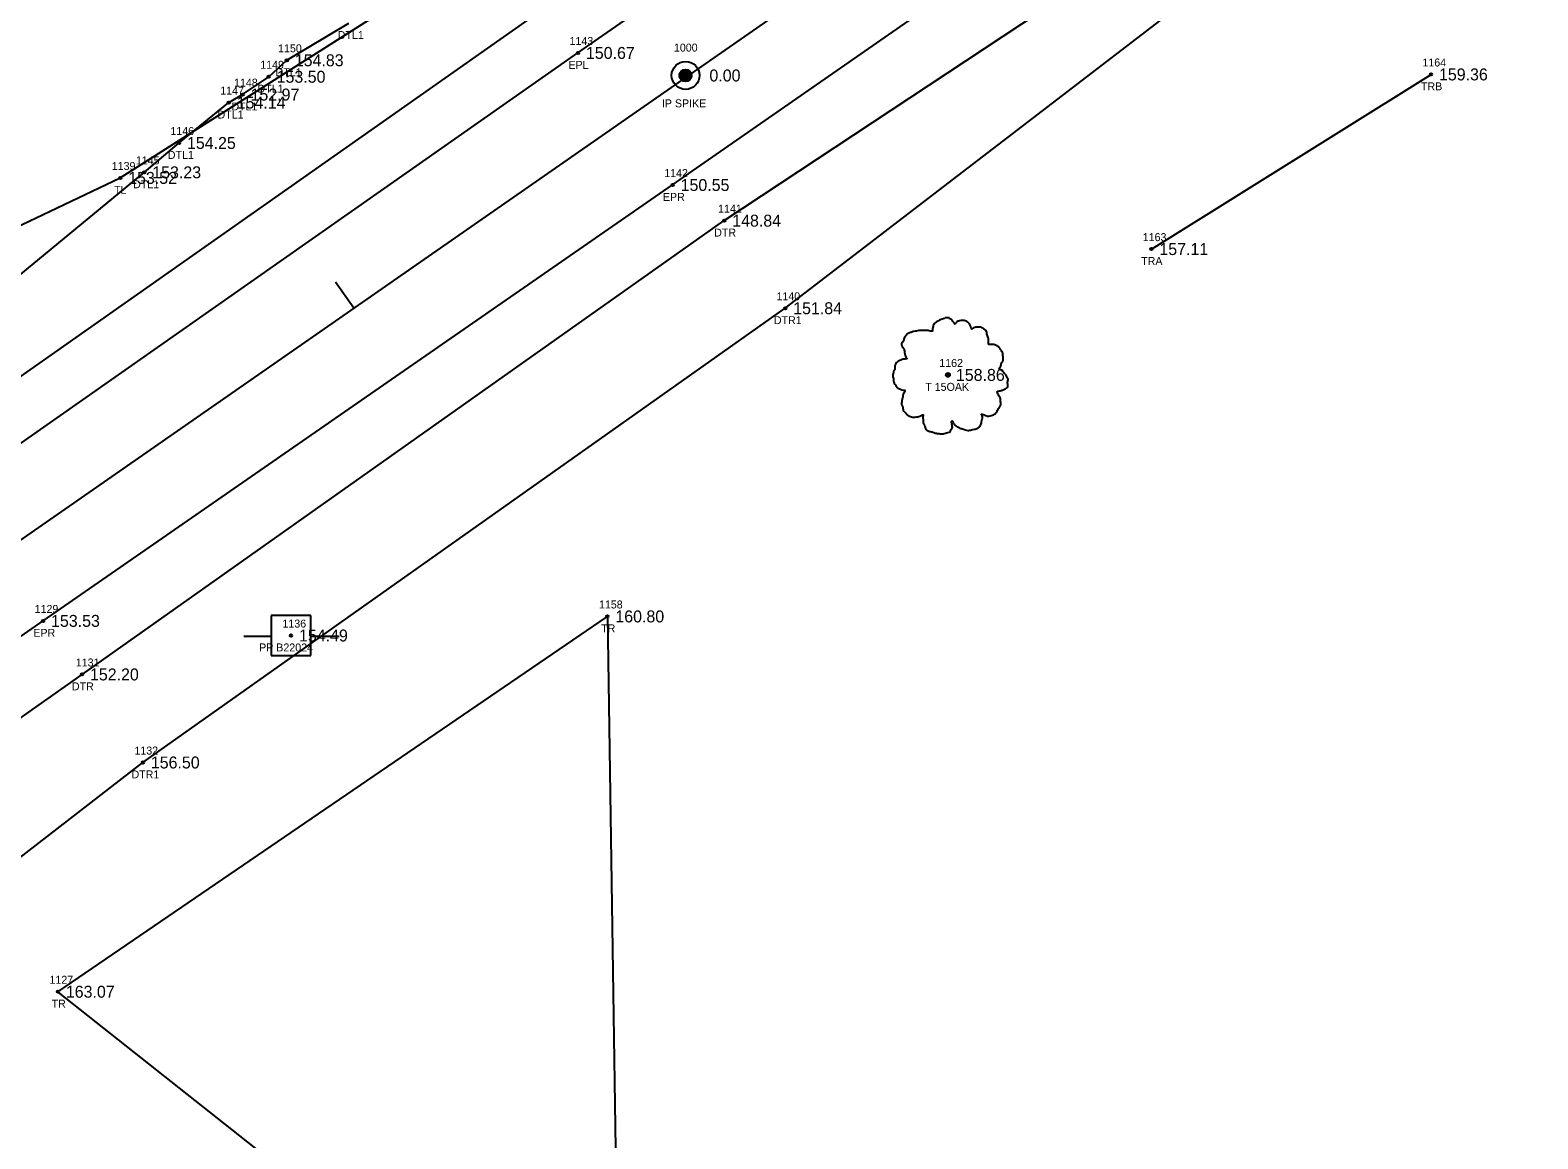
# Model space of a CAD drawing. Extents: x 2449052 to 2452984, y 1012343 to 1015262.
# Drawn here: x 2450486.8 to 2450676.2, y 1013470.3 to 1013609.6 of the extents above; entities that cross this region are included whole.
import ezdxf

# ---------------------------------------------------------------- set-up
doc = ezdxf.new("R2010")
doc.units = 0
for name, color, linetype in [('RD_EX_DV_Prop_txCode', 7, 'Continuous'), ('RD_EX_DV_PropPin', 7, 'Continuous'), ('RD_EX_H2O', 7, 'Continuous'), ('RD_EX_H2O_txCode', 7, 'Continuous'), ('RD_EX_Road', 7, 'Continuous'), ('RD_EX_Road_txCode', 7, 'Continuous'), ('RD_EX_TX_DV_Prop_ELEV', 7, 'Continuous'), ('RD_EX_TX_H2O_ELEV', 7, 'Continuous'), ('RD_EX_TX_Road_ELEV', 7, 'Continuous'), ('RD_EX_TX_VEG_ELEV', 7, 'Continuous'), ('RD_EX_UT', 7, 'Continuous'), ('RD_EX_UT_txCode', 7, 'Continuous'), ('RD_EX_VEG', 7, 'Continuous'), ('RD_EX_VEG_txCode', 7, 'Continuous'), ('RD_HC_Cl', 7, 'Continuous'), ('RD_HC_Data_Tic', 7, 'Continuous'), ('RD_HC_Survey_ELEV', 7, 'Continuous'), ('RD_SMD_Locator', 7, 'Continuous')]:
    doc.layers.add(name, color=color, linetype=linetype)

msp = doc.modelspace()

# ---------------------------------------------------------------- linework, layer by layer
at = {"layer": 'RD_EX_DV_PropPin'}
for p, q in [((2450568.38, 1013603.7), (2450568.38, 1013604.09)), ((2450568.42, 1013603.6), (2450568.42, 1013604.19)), ((2450568.45, 1013603.53), (2450568.45, 1013604.27)), ((2450568.49, 1013603.47), (2450568.49, 1013604.32)), ((2450568.52, 1013603.42), (2450568.52, 1013604.37)), ((2450568.56, 1013603.38), (2450568.56, 1013604.41)), ((2450568.59, 1013603.35), (2450568.59, 1013604.45)), ((2450568.63, 1013603.31), (2450568.63, 1013604.48)), ((2450568.66, 1013603.29), (2450568.66, 1013604.51)), ((2450568.7, 1013603.26), (2450568.7, 1013604.53)), ((2450568.73, 1013603.24), (2450568.73, 1013604.55)), ((2450568.77, 1013603.22), (2450568.77, 1013604.57)), ((2450568.8, 1013603.2), (2450568.8, 1013604.59)), ((2450568.84, 1013603.19), (2450568.84, 1013604.6)), ((2450568.87, 1013603.18), (2450568.87, 1013604.62)), ((2450568.91, 1013603.17), (2450568.91, 1013604.63)), ((2450568.94, 1013603.16), (2450568.94, 1013604.64)), ((2450568.98, 1013603.15), (2450568.98, 1013604.64)), ((2450569.01, 1013603.14), (2450569.01, 1013604.65)), ((2450569.05, 1013603.14), (2450569.05, 1013604.65)), ((2450569.08, 1013603.14), (2450569.08, 1013604.66)), ((2450569.12, 1013603.14), (2450569.12, 1013604.66)), ((2450569.15, 1013603.14), (2450569.15, 1013604.66)), ((2450569.19, 1013603.14), (2450569.19, 1013604.65)), ((2450569.22, 1013603.14), (2450569.22, 1013604.65)), ((2450569.26, 1013603.15), (2450569.26, 1013604.64)), ((2450569.29, 1013603.16), (2450569.29, 1013604.64)), ((2450569.33, 1013603.17), (2450569.33, 1013604.63)), ((2450569.36, 1013603.18), (2450569.36, 1013604.62)), ((2450569.4, 1013603.19), (2450569.4, 1013604.6)), ((2450569.44, 1013603.2), (2450569.44, 1013604.59)), ((2450569.47, 1013603.22), (2450569.47, 1013604.57)), ((2450569.51, 1013603.24), (2450569.51, 1013604.55)), ((2450569.54, 1013603.26), (2450569.54, 1013604.53)), ((2450569.58, 1013603.29), (2450569.58, 1013604.51)), ((2450569.61, 1013603.31), (2450569.61, 1013604.48)), ((2450569.65, 1013603.35), (2450569.65, 1013604.45)), ((2450569.68, 1013603.38), (2450569.68, 1013604.41)), ((2450569.72, 1013603.42), (2450569.72, 1013604.37)), ((2450569.75, 1013603.47), (2450569.75, 1013604.32)), ((2450569.79, 1013603.53), (2450569.79, 1013604.27)), ((2450569.82, 1013603.6), (2450569.82, 1013604.19)), ((2450569.86, 1013603.7), (2450569.86, 1013604.09))]:
    msp.add_line(p, q, dxfattribs=at)
for radius in [1.75, 0.761]:
    msp.add_circle((2450569.12, 1013603.9), radius, dxfattribs=at)
at = {"layer": 'RD_EX_H2O'}
for points in [[(2450167.46, 1013291.72), (2450167.1, 1013295.75), (2450175.19, 1013302.21), (2450253.51, 1013357.72), (2450334.87, 1013415.7), (2450415.19, 1013473.64), (2450493.27, 1013528.65), (2450573.99, 1013585.66), (2450651, 1013636.62), (2450748.48, 1013707.64), (2450786.48, 1013731.51)], [(2450167.46, 1013291.72), (2450171.71, 1013290.19), (2450180.8, 1013296.66), (2450259.89, 1013349.14), (2450344.33, 1013402.02), (2450412.23, 1013445.13), (2450424.15, 1013461.12), (2450474.5, 1013497.19), (2450500.92, 1013517.59), (2450581.65, 1013574.66), (2450655.67, 1013631.45), (2450753.63, 1013700.7), (2450792.21, 1013722.47), (2450790.93, 1013725.57), (2450786.48, 1013731.51)], [(2450082.81, 1013302.86), (2450086.85, 1013297.03), (2450148.02, 1013337.87), (2450230.55, 1013392.65), (2450311.52, 1013448.88), (2450394.54, 1013504.43), (2450473.16, 1013557.42), (2450552.01, 1013612.78), (2450577.68, 1013632.73), (2450594.53, 1013644.88)], [(2450469.06, 1013565.35), (2450501.1, 1013591.73), (2450505.46, 1013595.42), (2450511.71, 1013600.49), (2450513.45, 1013601.5), (2450516.73, 1013603.74), (2450519.01, 1013605.81), (2450526.82, 1013610.48)]]:
    msp.add_lwpolyline(points, dxfattribs=at)
at = {"layer": 'RD_EX_Road'}
for points in [[(2449674.89, 1012994.69), (2449752.35, 1013048.28), (2449834.92, 1013105.96), (2449914.72, 1013161.11), (2449995.66, 1013217.59), (2450075.29, 1013272.9), (2450081.34, 1013277.24), (2450093.41, 1013285.64), (2450155.49, 1013328.69), (2450236.05, 1013384.7), (2450317.88, 1013441.24), (2450398.87, 1013497.28), (2450477.09, 1013551.76), (2450555.6, 1013606.73), (2450600.18, 1013637.7), (2450618.08, 1013649.65), (2450627.95, 1013656.57), (2450636.43, 1013662.28), (2450733.79, 1013730.39), (2450811.43, 1013784.18), (2450891.39, 1013839.9), (2450907.04, 1013850.14)], [(2449685.94, 1012977.62), (2449764.81, 1013032.3), (2449846, 1013088.39), (2449925.85, 1013144.07), (2450006.8, 1013200.56), (2450086.45, 1013256.14), (2450125.67, 1013283.43), (2450163.55, 1013309.93), (2450166.36, 1013312.09), (2450247.44, 1013367.98), (2450329.19, 1013424.41), (2450410.32, 1013481.09), (2450488.38, 1013535.38), (2450567.5, 1013590.14), (2450648.09, 1013646.13), (2450745.08, 1013713.3), (2450823, 1013767.39), (2450902.19, 1013823.2), (2450918.14, 1013833.95)]]:
    msp.add_lwpolyline(points, dxfattribs=at)
at = {"layer": 'RD_EX_UT'}
for p, q in [((2450522.03, 1013536.04), (2450517.03, 1013536.04)), ((2450517.03, 1013536.04), (2450517.03, 1013531.04)), ((2450522.03, 1013531.04), (2450522.03, 1013536.04)), ((2450513.6, 1013533.48), (2450517.07, 1013533.48)), ((2450521.96, 1013533.48), (2450525.6, 1013533.48)), ((2450517.03, 1013531.04), (2450522.03, 1013531.04))]:
    msp.add_line(p, q, dxfattribs=at)
at = {"layer": 'RD_EX_VEG'}
msp.add_line((2450627.67, 1013582.09), (2450662.81, 1013604.03), dxfattribs=at)
for points in [[(2450316.02, 1013471.19), (2450462.83, 1013574.31), (2450498.07, 1013591.03), (2450546.15, 1013621.61), (2450588.36, 1013653.6), (2450578.07, 1013665.51), (2450498.03, 1013726.8)], [(2450560.85, 1013432.9), (2450490.24, 1013488.79), (2450559.3, 1013535.94), (2450560.85, 1013432.9)]]:
    msp.add_lwpolyline(points, dxfattribs=at)
for centre, radius in [((2450602.1, 1013566.28), 0.25), ((2450602.09, 1013566.26), 0.0001)]:
    msp.add_circle(centre, radius, dxfattribs=at)
for points in [[(2450602.23, 1013573.44), (2450601.93, 1013573.47), (2450601.61, 1013573.37), (2450601.36, 1013573.27), (2450601.13, 1013573.19), (2450600.91, 1013573.09), (2450600.61, 1013572.92), (2450600.38, 1013572.72), (2450600.26, 1013572.47), (2450600.21, 1013572.24), (2450600.16, 1013571.97), (2450600.16, 1013571.79), (2450600.03, 1013571.77), (2450599.88, 1013571.79), (2450599.63, 1013571.87), (2450599.38, 1013571.87), (2450599.13, 1013571.87), (2450598.78, 1013571.84), (2450598.43, 1013571.84), (2450598.16, 1013571.79), (2450597.83, 1013571.74), (2450597.46, 1013571.62), (2450597.11, 1013571.49), (2450596.81, 1013571.24), (2450596.56, 1013570.77), (2450596.43, 1013570.42), (2450596.28, 1013570.17), (2450596.43, 1013569.72), (2450596.61, 1013569.37), (2450596.63, 1013569.17), (2450596.71, 1013568.75), (2450596.81, 1013568.52), (2450596.93, 1013568.32), (2450596.86, 1013568.3), (2450596.48, 1013568.25), (2450596.18, 1013568.15), (2450595.76, 1013567.92), (2450595.54, 1013567.7), (2450595.44, 1013567.37), (2450595.41, 1013567.02), (2450595.31, 1013566.82), (2450595.24, 1013566.55), (2450595.21, 1013566.47), (2450595.16, 1013566.15), (2450595.26, 1013565.7), (2450595.29, 1013565.35), (2450595.41, 1013565.12), (2450595.56, 1013564.95), (2450595.73, 1013564.7), (2450596.13, 1013564.47), (2450596.46, 1013564.37), (2450596.66, 1013564.35), (2450596.48, 1013563.85), (2450596.43, 1013563.5), (2450596.31, 1013563.1), (2450596.31, 1013563.02), (2450596.26, 1013562.55), (2450596.41, 1013562.22), (2450596.48, 1013561.85), (2450596.66, 1013561.62), (2450596.93, 1013561.32), (2450597.26, 1013561.1), (2450597.76, 1013560.97), (2450598.16, 1013561), (2450598.73, 1013561.17), (2450598.98, 1013561.25), (2450598.96, 1013561.07), (2450598.98, 1013560.7), (2450598.98, 1013560.27), (2450599.13, 1013559.95), (2450599.23, 1013559.68), (2450599.38, 1013559.43), (2450599.71, 1013559.2), (2450600.11, 1013559.13), (2450600.53, 1013558.98), (2450600.98, 1013558.9), (2450601.48, 1013558.88), (2450602.08, 1013559.03), (2450602.36, 1013559.15), (2450602.46, 1013559.33), (2450602.66, 1013559.7), (2450602.61, 1013559.92), (2450602.63, 1013560.52), (2450602.73, 1013560.35), (2450602.91, 1013560), (2450603.41, 1013559.7), (2450603.81, 1013559.53), (2450604.28, 1013559.38), (2450604.58, 1013559.3), (2450605.06, 1013559.38), (2450605.43, 1013559.45), (2450605.81, 1013559.58), (2450606.11, 1013559.85), (2450606.28, 1013560.12), (2450606.33, 1013560.4), (2450606.41, 1013560.77), (2450606.46, 1013560.95)], [(2450606.46, 1013560.95), (2450606.38, 1013561.12), (2450606.33, 1013561.37), (2450606.41, 1013561.35), (2450606.58, 1013561.3), (2450606.86, 1013561.17), (2450607.08, 1013561.1), (2450607.4, 1013561.12), (2450607.68, 1013561.22), (2450608.13, 1013561.5), (2450608.4, 1013561.97), (2450608.68, 1013562.37), (2450608.75, 1013562.7), (2450608.7, 1013562.92), (2450608.68, 1013563.42), (2450608.48, 1013563.67), (2450608.43, 1013563.8), (2450608.33, 1013564.2), (2450608.4, 1013564.25), (2450608.68, 1013564.3), (2450609.05, 1013564.42), (2450609.33, 1013564.55), (2450609.55, 1013564.72), (2450609.63, 1013564.95), (2450609.6, 1013565.35), (2450609.65, 1013565.75), (2450609.58, 1013565.9), (2450609.48, 1013566.05), (2450609.4, 1013566.25), (2450609.25, 1013566.4), (2450609.15, 1013566.55), (2450609.05, 1013566.65), (2450608.93, 1013566.8), (2450608.75, 1013566.92), (2450608.6, 1013566.97), (2450608.55, 1013567.12), (2450608.7, 1013567.32), (2450608.75, 1013567.42), (2450608.78, 1013567.65), (2450609, 1013568), (2450609.05, 1013568.4), (2450609, 1013568.82), (2450608.95, 1013569.1), (2450608.8, 1013569.37), (2450608.6, 1013569.62), (2450608.48, 1013569.8), (2450608.3, 1013569.92), (2450607.98, 1013570.05), (2450607.73, 1013570.1), (2450607.38, 1013570.1), (2450607.18, 1013570.15), (2450607.2, 1013570.2), (2450607.2, 1013570.35), (2450607.2, 1013570.62), (2450607.13, 1013571.07), (2450606.98, 1013571.57), (2450606.98, 1013571.59), (2450606.88, 1013571.84), (2450606.66, 1013572.04), (2450606.48, 1013572.14), (2450606.28, 1013572.27), (2450606.03, 1013572.29), (2450605.73, 1013572.29), (2450605.46, 1013572.24), (2450605.26, 1013572.14), (2450605.08, 1013572.02), (2450605.01, 1013572.17), (2450604.91, 1013572.47), (2450604.86, 1013572.62), (2450604.71, 1013572.79), (2450604.48, 1013572.99), (2450604.03, 1013573.12), (2450603.41, 1013573.04), (2450603.11, 1013572.84), (2450602.96, 1013572.67), (2450602.91, 1013572.79), (2450602.71, 1013572.99), (2450602.61, 1013573.17), (2450602.43, 1013573.29), (2450602.28, 1013573.39), (2450602.18, 1013573.44)]]:
    msp.add_spline(points, degree=3, dxfattribs=at)
at = {"layer": 'RD_HC_Cl'}
msp.add_line((2449680.91, 1012986.23), (2452350.19, 1014841.68), dxfattribs=at)
at = {"layer": 'RD_HC_Data_Tic'}
msp.add_line((2450527.42, 1013574.65), (2450525.13, 1013577.93), dxfattribs=at)
at = {"layer": 'RD_SMD_Locator'}
for centre in [(2450519.01, 1013605.81), (2450555.6, 1013606.73), (2450516.73, 1013603.74), (2450569.12, 1013603.9), (2450662.81, 1013604.03), (2450511.71, 1013600.49), (2450513.45, 1013601.5), (2450505.46, 1013595.42), (2450498.07, 1013591.03), (2450501.1, 1013591.73), (2450567.5, 1013590.14), (2450573.99, 1013585.66), (2450627.67, 1013582.09), (2450581.65, 1013574.66), (2450602.1, 1013566.28), (2450559.3, 1013535.94), (2450488.38, 1013535.38), (2450519.54, 1013533.54), (2450493.27, 1013528.65), (2450500.92, 1013517.59), (2450490.24, 1013488.79)]:
    msp.add_circle(centre, 0.15, dxfattribs=at)

# ---------------------------------------------------------------- texts
at = {"layer": 'RD_EX_DV_Prop_txCode'}
for s, p in [('1000', (2450567.66, 1013606.9)), ('IP SPIKE', (2450566.15, 1013599.9))]:
    msp.add_text(s, height=1, dxfattribs=at).set_placement(p)
at = {"layer": 'RD_EX_H2O_txCode'}
for s, p in [('1150', (2450517.91, 1013606.81)), ('DTL1', (2450525.41, 1013608.48)), ('1149', (2450515.67, 1013604.74)), ('DTL1', (2450517.6, 1013603.81)), ('1147', (2450510.64, 1013601.49)), ('1148', (2450512.38, 1013602.5)), ('DTL1', (2450515.32, 1013601.74)), ('DTL1', (2450512.04, 1013599.5)), ('DTL1', (2450510.3, 1013598.49)), ('1146', (2450504.38, 1013596.42)), ('DTL1', (2450504.05, 1013593.42)), ('1145', (2450500.04, 1013592.73)), ('DTL1', (2450499.69, 1013589.73)), ('1141', (2450573.21, 1013586.66)), ('DTR', (2450572.72, 1013583.66)), ('1140', (2450580.55, 1013575.66)), ('DTR1', (2450580.22, 1013572.66)), ('1131', (2450492.49, 1013529.65)), ('DTR', (2450492, 1013526.65)), ('1132', (2450499.86, 1013518.59)), ('DTR1', (2450499.49, 1013515.59))]:
    msp.add_text(s, height=1, dxfattribs=at).set_placement(p)
at = {"layer": 'RD_EX_Road_txCode'}
for s, p in [('1143', (2450554.54, 1013607.73)), ('EPL', (2450554.4, 1013604.73)), ('1142', (2450566.44, 1013591.14)), ('EPR', (2450566.27, 1013588.14)), ('1129', (2450487.32, 1013536.38)), ('EPR', (2450487.15, 1013533.38))]:
    msp.add_text(s, height=1, dxfattribs=at).set_placement(p)
at = {"layer": 'RD_EX_TX_DV_Prop_ELEV'}
msp.add_text('0.00', height=1.5, dxfattribs=at).set_placement((2450572.12, 1013603.15))
at = {"layer": 'RD_EX_TX_H2O_ELEV'}
for s, p in [('154.83', (2450520.01, 1013605.06)), ('153.50', (2450517.73, 1013602.99)), ('152.97', (2450514.45, 1013600.75)), ('154.14', (2450512.71, 1013599.74)), ('154.25', (2450506.46, 1013594.67)), ('153.23', (2450502.1, 1013590.98)), ('148.84', (2450574.99, 1013584.91)), ('151.84', (2450582.65, 1013573.91)), ('152.20', (2450494.27, 1013527.9)), ('156.50', (2450501.92, 1013516.84))]:
    msp.add_text(s, height=1.5, dxfattribs=at).set_placement(p)
at = {"layer": 'RD_EX_TX_Road_ELEV'}
for s, p in [('150.67', (2450556.6, 1013605.98)), ('150.55', (2450568.5, 1013589.39)), ('153.53', (2450489.38, 1013534.63))]:
    msp.add_text(s, height=1.5, dxfattribs=at).set_placement(p)
at = {"layer": 'RD_EX_TX_VEG_ELEV'}
for s, p in [('159.36', (2450663.81, 1013603.28)), ('153.52', (2450499.07, 1013590.28)), ('157.11', (2450628.67, 1013581.34)), ('158.86', (2450603.1, 1013565.53)), ('160.80', (2450560.3, 1013535.19)), ('163.07', (2450491.24, 1013488.04))]:
    msp.add_text(s, height=1.5, dxfattribs=at).set_placement(p)
at = {"layer": 'RD_EX_UT_txCode'}
for s, p in [('1136', (2450518.46, 1013534.54)), ('PP B22024', (2450515.53, 1013531.54))]:
    msp.add_text(s, height=1, dxfattribs=at).set_placement(p)
at = {"layer": 'RD_EX_VEG_txCode'}
for s, p in [('1164', (2450661.73, 1013605.03)), ('TRB', (2450661.54, 1013602.03)), ('1139', (2450497.01, 1013592.03)), ('TL', (2450497.3, 1013589.03)), ('1163', (2450626.58, 1013583.09)), ('TRA', (2450626.38, 1013580.09)), ('1162', (2450601.01, 1013567.28)), ('T 15OAK', (2450599.25, 1013564.28)), ('1158', (2450558.24, 1013536.94)), ('TR', (2450558.51, 1013533.94)), ('1127', (2450489.18, 1013489.79)), ('TR', (2450489.45, 1013486.79))]:
    msp.add_text(s, height=1, dxfattribs=at).set_placement(p)
at = {"layer": 'RD_HC_Survey_ELEV'}
msp.add_text('154.49', height=1.5, dxfattribs=at).set_placement((2450520.54, 1013532.79))

doc.saveas('drawing.dxf')
